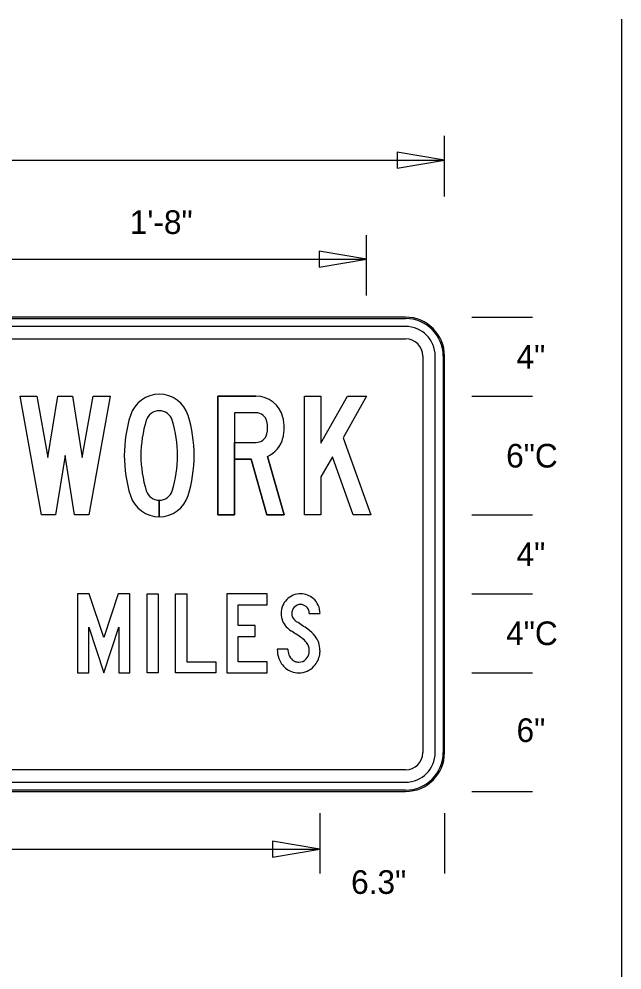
# Model space of a CAD drawing. Extents: x 0 to 770, y 0 to 495.
# Drawn here: x 103.2 to 192.5, y 354.3 to 495 of the extents above; entities that cross this region are included whole.
import ezdxf

# ---------------------------------------------------------------- set-up
doc = ezdxf.new("R2010")
doc.units = 0
for name, color, linetype in [('Dimension', 7, 'Continuous'), ('GSColorFill', 7, 'Continuous'), ('GSDims', 7, 'Continuous'), ('SheetLines_dp', 7, 'Continuous'), ('TextStructures', 7, 'Continuous')]:
    doc.layers.add(name, color=color, linetype=linetype)

msp = doc.modelspace()

# ---------------------------------------------------------------- linework, layer by layer
at = {"layer": 'Dimension'}
for points in [[(166.21, 474.11), (159.19, 475.3), (159.19, 472.93)], [(154.67, 459.44), (147.65, 460.63), (147.65, 458.25)], [(147.77, 372.12), (140.76, 373.31), (140.76, 370.93)]]:
    msp.add_lwpolyline(points, close=True, dxfattribs=at)
at = {"layer": 'GSColorFill'}
for p, q in [((160.45, 450.87), (31.6, 450.87)), ((31.6, 450.69), (160.45, 450.69)), ((160.45, 449.5), (31.6, 449.5)), ((31.6, 447.67), (160.45, 447.67)), ((163.01, 445.11), (163.01, 386.44)), ((164.84, 386.44), (164.84, 445.11)), ((166.02, 445.11), (166.02, 386.44)), ((166.21, 386.44), (166.21, 445.11)), ((138.29, 439.17), (132.65, 439.17)), ((138.29, 436.72), (138.29, 436.72)), ((138.29, 432.33), (138.29, 432.33)), ((138.29, 432.33), (138.29, 432.33)), ((123.97, 423.78), (123.97, 421.32)), ((123.97, 421.32), (123.97, 423.78)), ((123.97, 423.78), (123.97, 421.32)), ((123.97, 421.32), (123.97, 423.78)), ((160.45, 383.89), (31.62, 383.89)), ((31.62, 382.06), (160.45, 382.06)), ((160.45, 380.87), (31.6, 380.87)), ((31.6, 380.69), (160.45, 380.69))]:
    msp.add_line(p, q, dxfattribs=at)
for points in [[(107.48, 430.09), (108.93, 439.17), (111.1, 439.17), (112.55, 430.09), (114.19, 439.17), (116.68, 439.17), (113.53, 421.63), (111.42, 421.63), (110.02, 430.4), (108.61, 421.63), (106.51, 421.63), (103.35, 439.17), (105.84, 439.17)], [(107.48, 430.09), (108.93, 439.17), (111.1, 439.17), (112.55, 430.09), (114.19, 439.17), (116.68, 439.17), (113.53, 421.63), (111.42, 421.63), (110.02, 430.4), (108.61, 421.63), (106.51, 421.63), (103.35, 439.17), (105.84, 439.17)], [(107.48, 430.09), (108.93, 439.17), (111.1, 439.17), (112.55, 430.09), (114.19, 439.17), (116.68, 439.17), (113.53, 421.63), (111.42, 421.63), (110.02, 430.4), (108.61, 421.63), (106.51, 421.63), (103.35, 439.17), (105.84, 439.17)], [(149.6, 430.21), (147.92, 427.24), (147.92, 421.63), (145.46, 421.63), (145.46, 439.17), (147.92, 439.17), (147.92, 432.23), (151.85, 439.17), (154.67, 439.17), (151.19, 433.03), (155.28, 421.63), (152.68, 421.63)], [(149.6, 430.21), (147.92, 427.24), (147.92, 421.63), (145.46, 421.63), (145.46, 439.17), (147.92, 439.17), (147.92, 432.23), (151.85, 439.17), (154.67, 439.17), (151.19, 433.03), (155.28, 421.63), (152.68, 421.63)], [(149.6, 430.21), (147.92, 427.24), (147.92, 421.63), (145.46, 421.63), (145.46, 439.17), (147.92, 439.17), (147.92, 432.23), (151.85, 439.17), (154.67, 439.17), (151.19, 433.03), (155.28, 421.63), (152.68, 421.63)], [(115.74, 398.23), (117.97, 404.97), (117.97, 398.23), (119.6, 398.23), (119.6, 409.93), (117.88, 409.93), (115.74, 403.46), (113.61, 409.93), (111.88, 409.93), (111.88, 398.23), (113.52, 398.23), (113.52, 404.97)], [(115.74, 398.23), (117.97, 404.97), (117.97, 398.23), (119.6, 398.23), (119.6, 409.93), (117.88, 409.93), (115.74, 403.46), (113.61, 409.93), (111.88, 409.93), (111.88, 398.23), (113.52, 398.23), (113.52, 404.97)], [(115.74, 398.23), (117.97, 404.97), (117.97, 398.23), (119.6, 398.23), (119.6, 409.93), (117.88, 409.93), (115.74, 403.46), (113.61, 409.93), (111.88, 409.93), (111.88, 398.23), (113.52, 398.23), (113.52, 404.97)], [(122.18, 409.93), (123.82, 409.93), (123.82, 398.23), (122.18, 398.23)], [(122.18, 409.93), (123.82, 409.93), (123.82, 398.23), (122.18, 398.23)], [(122.18, 409.93), (123.82, 409.93), (123.82, 398.23), (122.18, 398.23)], [(126.39, 409.93), (128.03, 409.93), (128.03, 399.87), (132.35, 399.87), (132.35, 398.23), (126.39, 398.23)], [(126.39, 409.93), (128.03, 409.93), (128.03, 399.87), (132.35, 399.87), (132.35, 398.23), (126.39, 398.23)], [(126.39, 409.93), (128.03, 409.93), (128.03, 399.87), (132.35, 399.87), (132.35, 398.23), (126.39, 398.23)], [(135.63, 399.87), (135.63, 403.61), (138.19, 403.61), (138.19, 405.25), (135.63, 405.25), (135.63, 408.29), (139.96, 408.29), (139.96, 409.93), (133.99, 409.93), (133.99, 398.23), (139.96, 398.23), (139.96, 399.87)], [(135.63, 399.87), (135.63, 403.61), (138.19, 403.61), (138.19, 405.25), (135.63, 405.25), (135.63, 408.29), (139.96, 408.29), (139.96, 409.93), (133.99, 409.93), (133.99, 398.23), (139.96, 398.23), (139.96, 399.87)], [(135.63, 399.87), (135.63, 403.61), (138.19, 403.61), (138.19, 405.25), (135.63, 405.25), (135.63, 408.29), (139.96, 408.29), (139.96, 409.93), (133.99, 409.93), (133.99, 398.23), (139.96, 398.23), (139.96, 399.87)]]:
    msp.add_lwpolyline(points, close=True, dxfattribs=at)
for points in [[(132.65, 439.17), (132.65, 421.63), (135.11, 421.63), (135.11, 429.87), (137.57, 429.87), (139.92, 421.63), (142.48, 421.63), (140.02, 430.26)], [(138.29, 436.72), (135.11, 436.72), (135.11, 421.63), (132.65, 421.63), (132.65, 439.17), (138.29, 439.17)], [(138.29, 436.72), (135.11, 436.72), (135.11, 421.63), (132.65, 421.63), (132.65, 439.17), (138.29, 439.17)], [(138.29, 436.72), (135.11, 436.72), (135.11, 432.33), (138.29, 432.33)], [(140.02, 430.26), (142.48, 421.63), (139.92, 421.63), (137.57, 429.87), (135.11, 429.87), (135.11, 432.33), (138.29, 432.33)], [(140.02, 430.26), (142.48, 421.63), (139.92, 421.63), (137.57, 429.87), (135.11, 429.87), (135.11, 432.33), (138.29, 432.33)], [(146.19, 407.02), (147.77, 407.02)], [(146.19, 407.02), (147.77, 407.02)], [(146.19, 407.02), (147.77, 407.02)], [(143.02, 401.76), (141.44, 401.76)], [(143.02, 401.76), (141.44, 401.76)], [(143.02, 401.76), (141.44, 401.76)]]:
    msp.add_lwpolyline(points, dxfattribs=at)
for centre, radius, start, end in [((160.45, 445.11), 5.76, 0, 90), ((160.45, 445.11), 5.57, 0, 90), ((160.45, 445.11), 4.39, 0, 90), ((160.45, 445.11), 2.56, 0, 90), ((123.97, 435.01), 4.47, 17.3283, 162.6717), ((123.97, 435.01), 4.47, 17.3283, 162.6717), ((123.97, 435.01), 4.47, 17.3283, 162.6717), ((138.29, 435.05), 4.12, 13.8865, 90), ((138.29, 435.05), 4.12, 13.8865, 90), ((138.29, 435.05), 4.12, 13.8865, 90), ((138.73, 430.4), 19.94, 162.6717, 197.3283), ((138.73, 430.4), 19.94, 162.6717, 197.3283), ((138.73, 430.4), 19.94, 162.6717, 197.3283), ((123.97, 435.01), 2.02, 17.3283, 162.6717), ((123.97, 435.01), 2.02, 17.3283, 162.6717), ((123.97, 435.01), 2.02, 17.3283, 162.6717), ((109.2, 430.4), 19.94, 342.6717, 17.3283), ((109.2, 430.4), 19.94, 342.6717, 17.3283), ((109.2, 430.4), 19.94, 342.6717, 17.3283), ((138.29, 435.05), 1.67, 13.8865, 90), ((138.29, 435.05), 1.67, 13.8865, 90), ((138.29, 435.05), 1.67, 13.8865, 90), ((138.73, 430.4), 17.48, 162.6717, 197.3283), ((138.73, 430.4), 17.48, 162.6717, 197.3283), ((138.73, 430.4), 17.48, 162.6717, 197.3283), ((109.2, 430.4), 17.48, 342.6717, 17.3283), ((109.2, 430.4), 17.48, 342.6717, 17.3283), ((109.2, 430.4), 17.48, 342.6717, 17.3283), ((136.16, 434.52), 3.86, 346.1135, 13.8865), ((136.16, 434.52), 3.86, 346.1135, 13.8865), ((136.16, 434.52), 3.86, 346.1135, 13.8865), ((136.16, 434.52), 6.32, 346.1135, 13.8865), ((136.16, 434.52), 6.32, 346.1135, 13.8865), ((136.16, 434.52), 6.32, 346.1135, 13.8865), ((138.29, 434), 1.67, 270, 346.1135), ((138.29, 434), 1.67, 270, 346.1135), ((138.29, 434), 1.67, 270, 346.1135), ((138.29, 434), 4.12, 294.8221, 346.1135), ((138.29, 434), 4.12, 294.8221, 346.1135), ((138.29, 434), 4.12, 294.8221, 346.1135), ((123.97, 425.79), 2.02, 197.3283, 342.6717), ((123.97, 425.79), 2.02, 197.3283, 270), ((123.97, 425.79), 2.02, 197.3283, 270), ((123.97, 425.79), 2.02, 270.0249, 342.6717), ((123.97, 425.79), 2.02, 270.0249, 342.6717), ((123.97, 425.79), 4.47, 197.3283, 342.6717), ((123.97, 425.79), 4.47, 197.3283, 270), ((123.97, 425.79), 4.47, 197.3283, 270), ((123.97, 425.79), 4.47, 270.0112, 342.6717), ((123.97, 425.79), 4.47, 270.0112, 342.6717), ((160.45, 386.44), 4.39, 270, 0), ((160.45, 386.44), 2.56, 270, 0), ((160.45, 386.44), 5.76, 270, 0), ((160.45, 386.44), 5.57, 270, 0)]:
    msp.add_arc(centre, radius, start, end, dxfattribs=at)
for centre, major_axis, start_param, end_param in [((144.91, 407.02), (0, 2.91), 6.283184, 7.853982), ((144.91, 407.02), (0, 2.91), 6.283184, 7.853982), ((144.91, 407.02), (0, 2.91), 6.283184, 7.853982), ((144.91, 407.12), (0, 2.81), 5.561989, 6.283185), ((144.91, 407.12), (0, 2.81), 5.561989, 6.283185), ((144.91, 407.12), (0, 2.81), 5.561989, 6.283185), ((144.91, 407.02), (0, 1.33), 6.283183, 7.853981), ((144.91, 407.02), (0, 1.33), 6.283183, 7.853981), ((144.91, 407.02), (0, 1.33), 6.283183, 7.853981), ((144.91, 407.12), (0, 1.23), 5.561989, 6.283185), ((144.91, 407.12), (0, 1.23), 5.561989, 6.283185), ((144.91, 407.12), (0, 1.23), 5.561989, 6.283185), ((144.82, 407.02), (0, 2.96), 4.712389, 5.561989), ((144.82, 407.02), (0, 2.96), 4.712389, 5.561989), ((144.82, 407.02), (0, 2.96), 4.712389, 5.561989), ((144.92, 407.02), (0, 2.92), 1.570796, 2.321595), ((144.92, 407.02), (0, 2.92), 1.570796, 2.321595), ((144.92, 407.02), (0, 2.92), 1.570796, 2.321595), ((144.92, 407.02), (0, 1.34), 1.570796, 2.321595), ((144.92, 407.02), (0, 1.34), 1.570796, 2.321595), ((144.92, 407.02), (0, 1.34), 1.570796, 2.321595), ((144.82, 407.02), (0, 1.37), 4.712389, 5.561989), ((144.82, 407.02), (0, 1.37), 4.712389, 5.561989), ((144.82, 407.02), (0, 1.37), 4.712389, 5.561989), ((145.4, 407.47), (0, 1.99), 2.321595, 2.56746), ((145.4, 407.47), (0, 1.99), 2.321595, 2.56746), ((145.4, 407.47), (0, 1.99), 2.321595, 2.56746), ((108.17, 349.92), (0, 66.55), 5.679143, 5.709053), ((108.17, 349.92), (0, 66.55), 5.679143, 5.709053), ((108.17, 349.92), (0, 66.55), 5.679143, 5.709053), ((145.4, 407.47), (0, 3.58), 2.321595, 2.56746), ((145.4, 407.47), (0, 3.58), 2.321595, 2.56746), ((145.4, 407.47), (0, 3.58), 2.321595, 2.56746), ((108.17, 349.92), (0, 64.97), 5.679143, 5.709053), ((108.17, 349.92), (0, 64.97), 5.679143, 5.709053), ((108.17, 349.92), (0, 64.97), 5.679143, 5.709053), ((143.2, 400.68), (0, 4.87), 5.373599, 5.679143), ((143.2, 400.68), (0, 4.87), 5.373599, 5.679143), ((143.2, 400.68), (0, 4.87), 5.373599, 5.679143), ((143.2, 400.68), (0, 3.29), 5.373599, 5.679143), ((143.2, 400.68), (0, 3.29), 5.373599, 5.679143), ((143.2, 400.68), (0, 3.29), 5.373599, 5.679143), ((144.33, 401.56), (0, 1.86), 4.712389, 5.373599), ((144.33, 401.56), (0, 1.86), 4.712389, 5.373599), ((144.33, 401.56), (0, 1.86), 4.712389, 5.373599), ((144.33, 401.56), (0, 3.44), 4.712389, 5.373599), ((144.33, 401.56), (0, 3.44), 4.712389, 5.373599), ((144.33, 401.56), (0, 3.44), 4.712389, 5.373599), ((145.61, 401.76), (0, 4.17), 1.570808, 1.909921), ((145.61, 401.76), (0, 4.17), 1.570808, 1.909921), ((145.61, 401.76), (0, 4.17), 1.570808, 1.909921), ((145.61, 401.76), (0, 2.59), 1.570816, 1.909918), ((145.61, 401.76), (0, 2.59), 1.570816, 1.909918), ((145.61, 401.76), (0, 2.59), 1.570816, 1.909918), ((144.41, 401.5), (0, 1.78), 3.967076, 4.552917), ((144.41, 401.5), (0, 1.78), 3.967076, 4.552917), ((144.41, 401.5), (0, 1.78), 3.967076, 4.552917), ((144.01, 401.56), (0, 2.18), 4.552917, 4.712389), ((144.01, 401.56), (0, 2.18), 4.552917, 4.712389), ((144.01, 401.56), (0, 2.18), 4.552917, 4.712389), ((144.01, 401.56), (0, 3.77), 4.552917, 4.712389), ((144.01, 401.56), (0, 3.77), 4.552917, 4.712389), ((144.01, 401.56), (0, 3.77), 4.552917, 4.712389), ((144.9, 401.51), (0, 3.41), 1.909925, 2.431476), ((144.9, 401.51), (0, 3.41), 1.909925, 2.431476), ((144.9, 401.51), (0, 3.41), 1.909925, 2.431476), ((144.9, 401.51), (0, 1.83), 1.909925, 2.431476), ((144.9, 401.51), (0, 1.83), 1.909925, 2.431476), ((144.9, 401.51), (0, 1.83), 1.909925, 2.431476), ((144.43, 400.97), (0, 1.12), 2.431476, 2.811358), ((144.43, 400.97), (0, 1.12), 2.431476, 2.811358), ((144.43, 400.97), (0, 1.12), 2.431476, 2.811358), ((144.63, 401.54), (0, 1.72), 2.811358, 3.141593), ((144.63, 401.54), (0, 1.72), 2.811358, 3.141593), ((144.63, 401.54), (0, 1.72), 2.811358, 3.141593), ((144.63, 401.29), (0, 1.48), 3.141593, 3.967076), ((144.63, 401.29), (0, 1.48), 3.141593, 3.967076), ((144.63, 401.29), (0, 1.48), 3.141593, 3.967076), ((144.41, 401.5), (0, 3.36), 3.967076, 4.552917), ((144.41, 401.5), (0, 3.36), 3.967076, 4.552917), ((144.41, 401.5), (0, 3.36), 3.967076, 4.552917), ((144.43, 400.97), (0, 2.7), 2.431476, 2.811358), ((144.43, 400.97), (0, 2.7), 2.431476, 2.811358), ((144.43, 400.97), (0, 2.7), 2.431476, 2.811358), ((144.63, 401.54), (0, 3.31), 2.811358, 3.141593), ((144.63, 401.54), (0, 3.31), 2.811358, 3.141593), ((144.63, 401.54), (0, 3.31), 2.811358, 3.141593), ((144.63, 401.29), (0, 3.06), 3.141593, 3.967076), ((144.63, 401.29), (0, 3.06), 3.141593, 3.967076), ((144.63, 401.29), (0, 3.06), 3.141593, 3.967076)]:
    msp.add_ellipse(centre, major_axis=major_axis, ratio=0.999997, start_param=start_param, end_param=end_param, dxfattribs=at)
at = {"layer": 'GSDims'}
for p, q in [((166.21, 468.74), (166.21, 477.7)), ((25.84, 474.11), (166.21, 474.11)), ((154.67, 454.07), (154.67, 463.02)), ((96.02, 459.44), (154.67, 459.44)), ((170.28, 450.87), (179.24, 450.87)), ((170.28, 439.17), (179.24, 439.17)), ((170.28, 439.17), (179.24, 439.17)), ((170.28, 421.63), (179.24, 421.63)), ((170.28, 409.94), (179.24, 409.94)), ((170.28, 398.24), (179.24, 398.24)), ((170.28, 380.69), (179.24, 380.69)), ((147.77, 377.49), (147.77, 368.54)), ((166.21, 377.49), (166.21, 368.54)), ((44.27, 372.12), (147.77, 372.12))]:
    msp.add_line(p, q, dxfattribs=at)
at = {"layer": 'SheetLines_dp'}
msp.add_line((192.5, 0), (192.5, 495), dxfattribs=at)

# ---------------------------------------------------------------- texts
at = {"layer": 'TextStructures'}
for s, p in [('1\'-8"', (119.6, 463.19)), ('4"', (176.88, 443.27)), ('6"C', (175.34, 428.62)), ('4"', (176.88, 414.03)), ('4"C', (175.34, 402.34)), ('6"', (176.88, 388)), ('6.3"', (152.38, 365.52))]:
    msp.add_text(s, height=3.5, dxfattribs=at).set_placement(p)

doc.saveas('drawing.dxf')
